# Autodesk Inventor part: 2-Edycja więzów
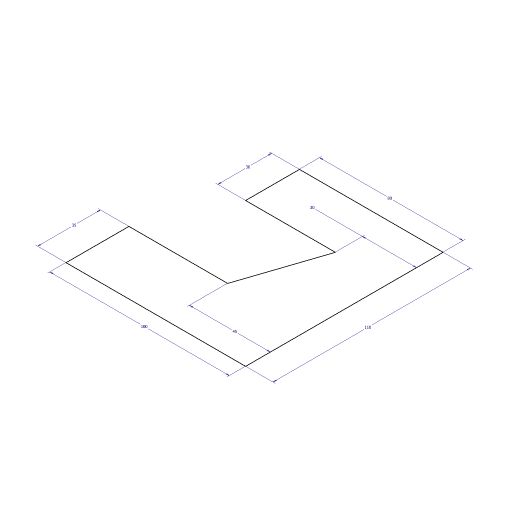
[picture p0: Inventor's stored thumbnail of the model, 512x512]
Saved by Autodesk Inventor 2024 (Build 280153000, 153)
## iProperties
Company: ATC
Shininess: 20.0
Length Units: 11269
Angle Units: 11279
Time Units: 11290
Mass Units: 11283
Length Display Precision: 1
Angle Display Precision: 1
Compacted: True
Created: 2023-03
Part Number: 2-Edycja więzów
Document SubType Name: Modeling
Designer: Andrzej Jaskulski
Material: Kurs-AJ
Density: 1 g/cm^3
Appearance: Kurs-AJ
Checked By: A.J.
Engr Approved By: Andrzej Jaskulski
Mfg Approved By: Andrzej Jaskulski
Authority: A.J.
Density: 0.0
Volumn: 0.0
Area: 0.0
PropertySet Name: Model Information
Control State: 0
Master: False
Checked Out: False
Title: A.J.: Kurs R2024-MEP
Author: Andrzej Jaskulski
Revision Number: 1/24
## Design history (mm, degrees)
sketch "Ceownik"
  geometry: L1 (-25.738, 9.563)-(74.262, 9.563); L2 (74.262, 9.563)-(74.262, 119.563); L3 (74.262, 119.563)-(-5.738, 119.563); L4 (-5.738, 119.563)-(-5.738, 89.563); L5 (-5.738, 89.563)-(44.262, 89.563); L6 (44.262, 89.563)-(29.262, 44.563); L7 (29.262, 44.563)-(-25.738, 44.563); L8 (-25.738, 44.563)-(-25.738, 9.563)
  constraints: 16 end point, 4 horizontal, 3 vertical, 1 other
  dimensions: "d1" = 100 distance of L1.start L1.end; "d2" = 110 distance of L1.end L2.end; "d3" = 80 distance of L2.end L3.end; "d4" = 30 distance of L3.end L4.end; "d5" = 35 distance of L7.end L1.start; "d6" = 45 distance from line of L2 L6.end; "d7" = 30 distance from line of L2 L5.end
node "Korpusy bryłowe"
node "Korpusy powierzchniowe"
